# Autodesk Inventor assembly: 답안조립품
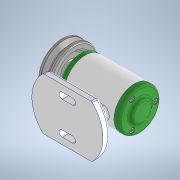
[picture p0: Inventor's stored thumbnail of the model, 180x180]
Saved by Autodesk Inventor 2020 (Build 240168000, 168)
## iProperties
Created: 2022-02
Part Number: 답안조립품
Document SubType Name: Assembly
Designer: 602-01
Author: 602-01
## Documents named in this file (14)
- C:\Users\602-01\Desktop\720206V1024\답안조립품.iam
- C:\Users\602-01\Desktop\720206V1024\720206V1024-1\본체.ipt
- C:\Users\602-01\Desktop\720206V1024\뒤커버.ipt
- C:\Users\602-01\Desktop\720206V1024\앞커버.ipt
- C:\Users\602-01\Desktop\720206V1024\축.ipt
- C:\Users\602-01\Desktop\720206V1024\베어링 6002.ipt
- C:\Users\602-01\Desktop\720206V1024\오일 실 15 x 25 x 7.ipt
- C:\Users\602-01\Desktop\720206V1024\V벨트풀리.ipt
- C:\Users\602-01\Desktop\720206V1024\키 3 x 3 x 12.ipt
- C:\Users\602-01\Desktop\720206V1024\평와셔 8 x 17.ipt
- C:\Users\602-01\Desktop\720206V1024\스프링와셔 8.ipt
- C:\Users\602-01\Desktop\720206V1024\너트 M8.ipt
- C:\Users\602-01\Desktop\720206V1024\볼트 M4 x 10.ipt
- C:\Users\602-01\Desktop\720206V1024\고무 캡.ipt
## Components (2 placed, 2 different names)
1. V벨트풀리:1
2. 고무 캡:1 — 각도:1
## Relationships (1: Angle 1)
- 각도:1 [Angle]: 고무 캡:1
